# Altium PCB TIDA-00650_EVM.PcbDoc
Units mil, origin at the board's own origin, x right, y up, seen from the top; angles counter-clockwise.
Board outline 1549.21 x 1156.5 mil, 4 copper layers (Component Side, Ground Plane, Power Plane, Solder Side), stack 33.234 mil thick; 52 components, 27 nets, 148 pads, 47 vias.
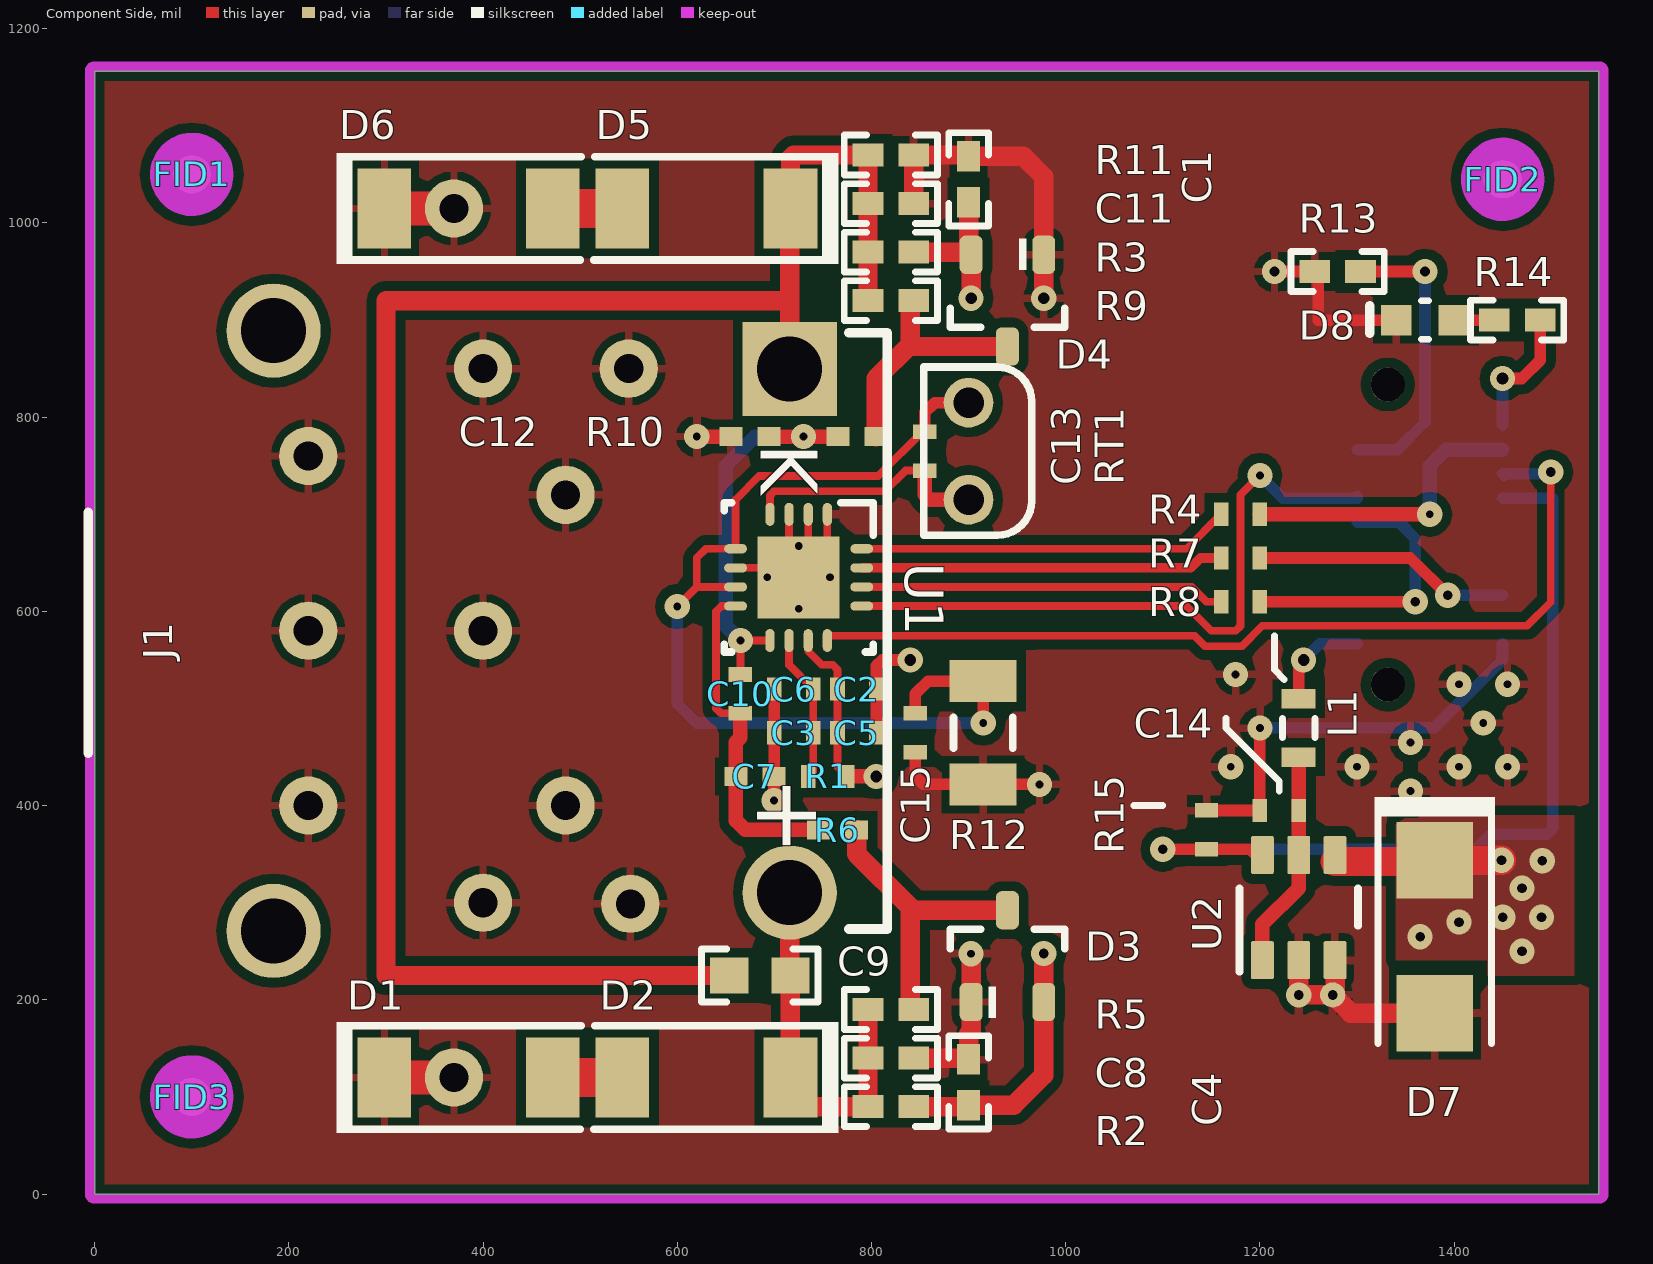
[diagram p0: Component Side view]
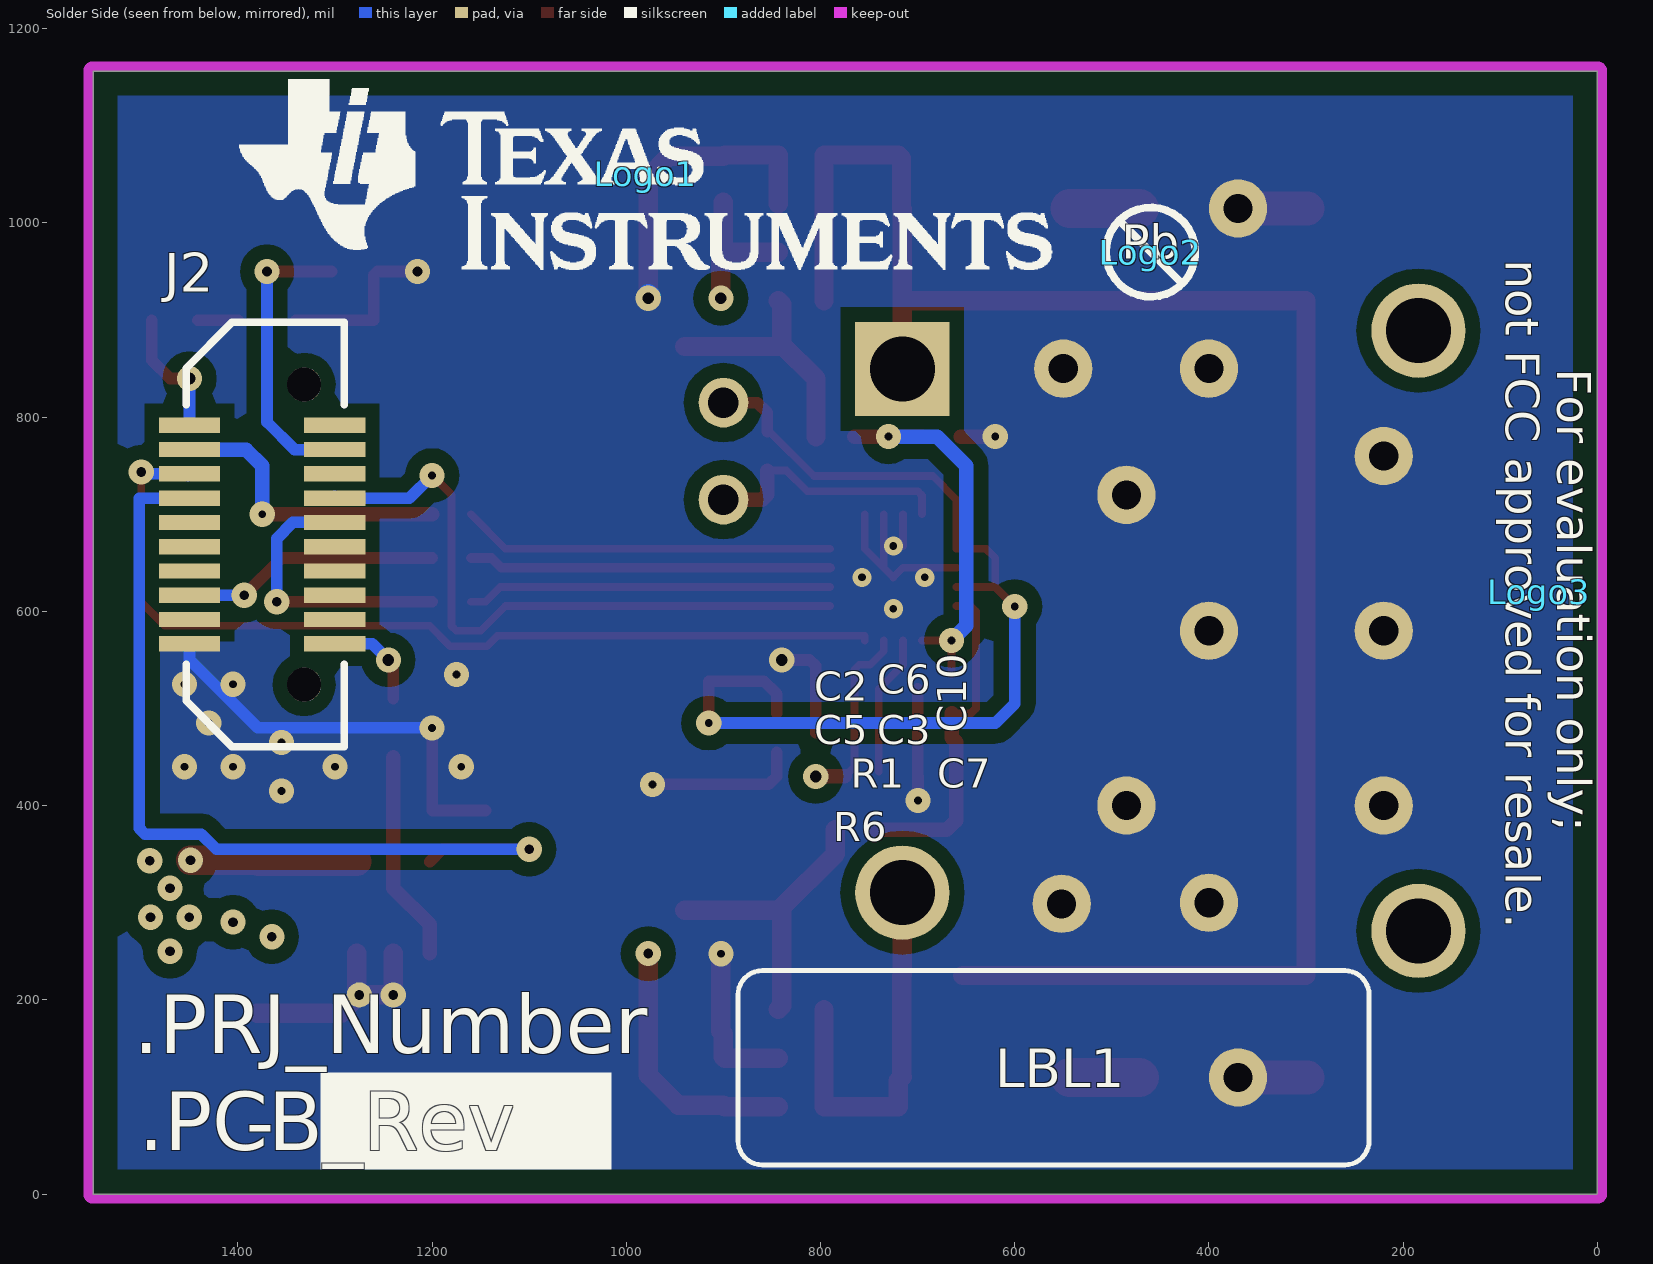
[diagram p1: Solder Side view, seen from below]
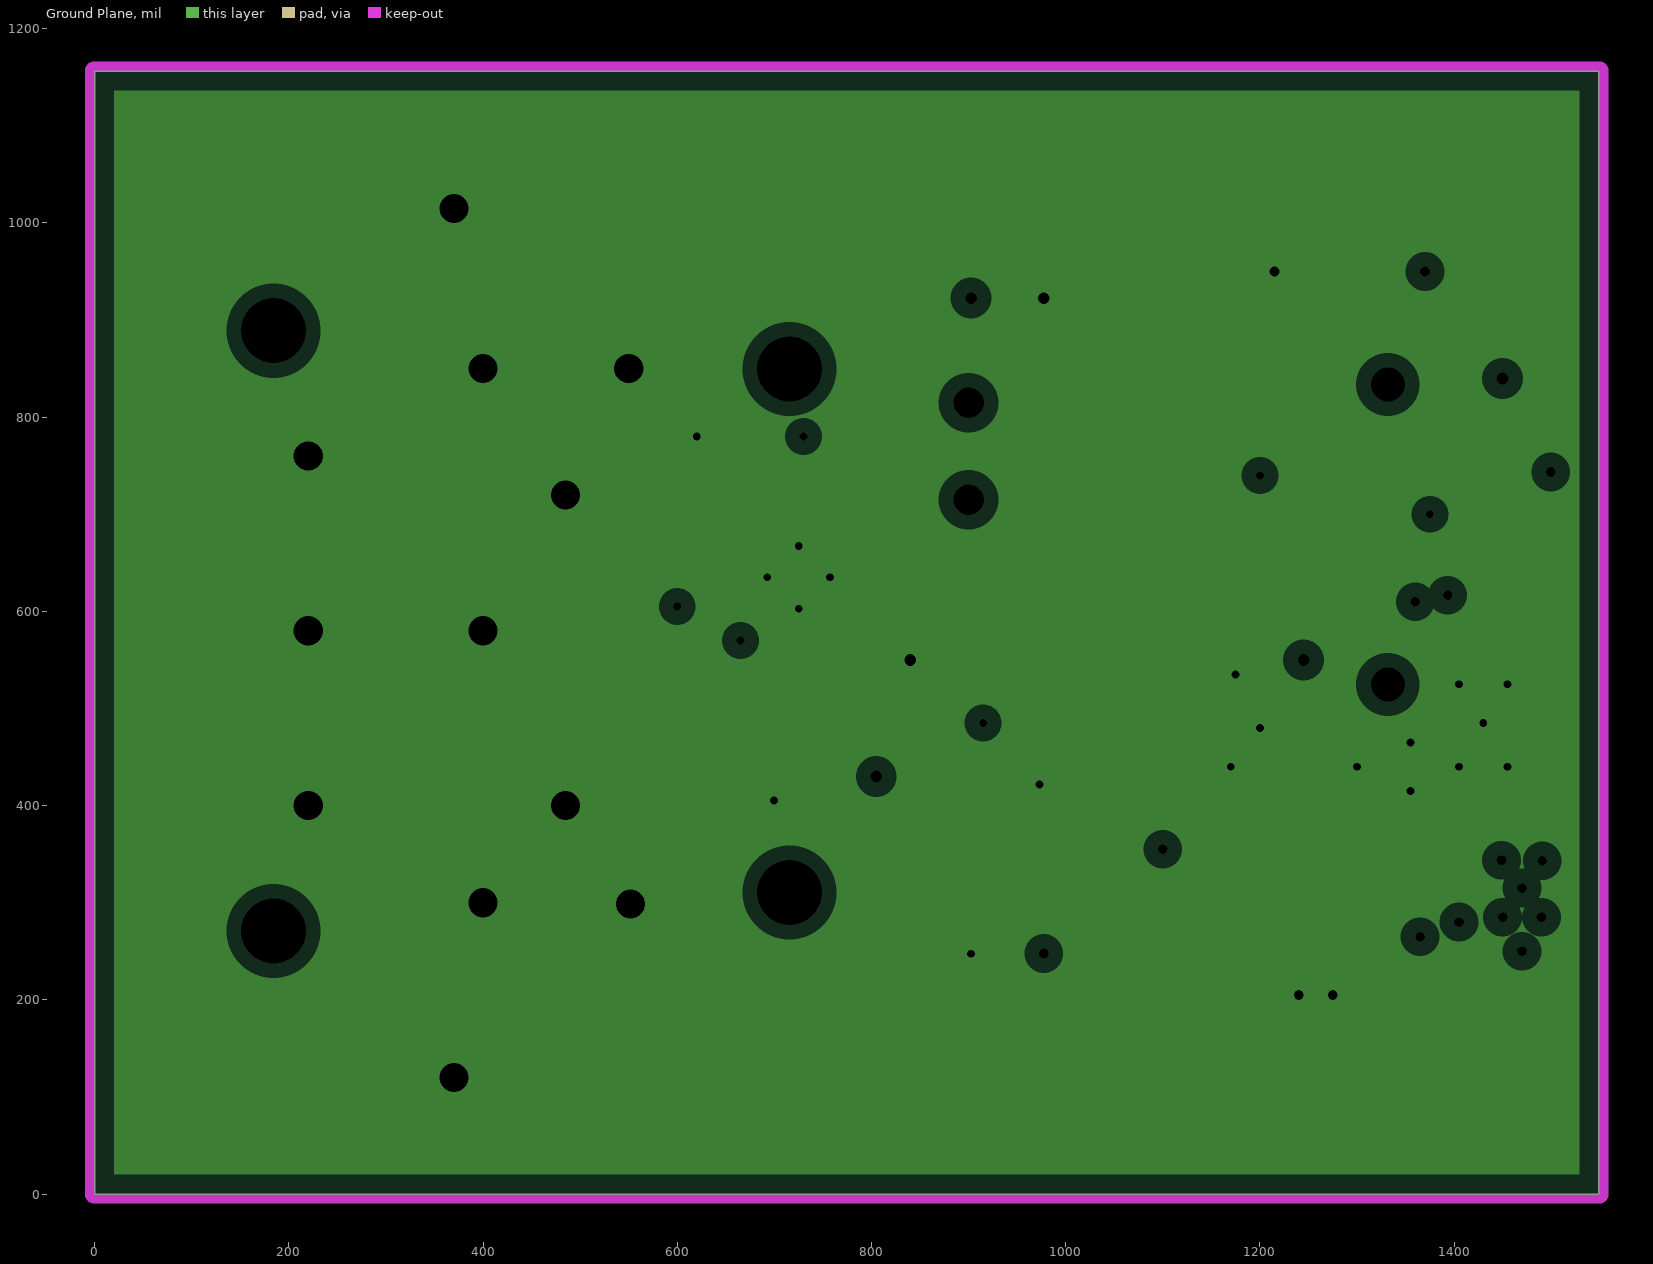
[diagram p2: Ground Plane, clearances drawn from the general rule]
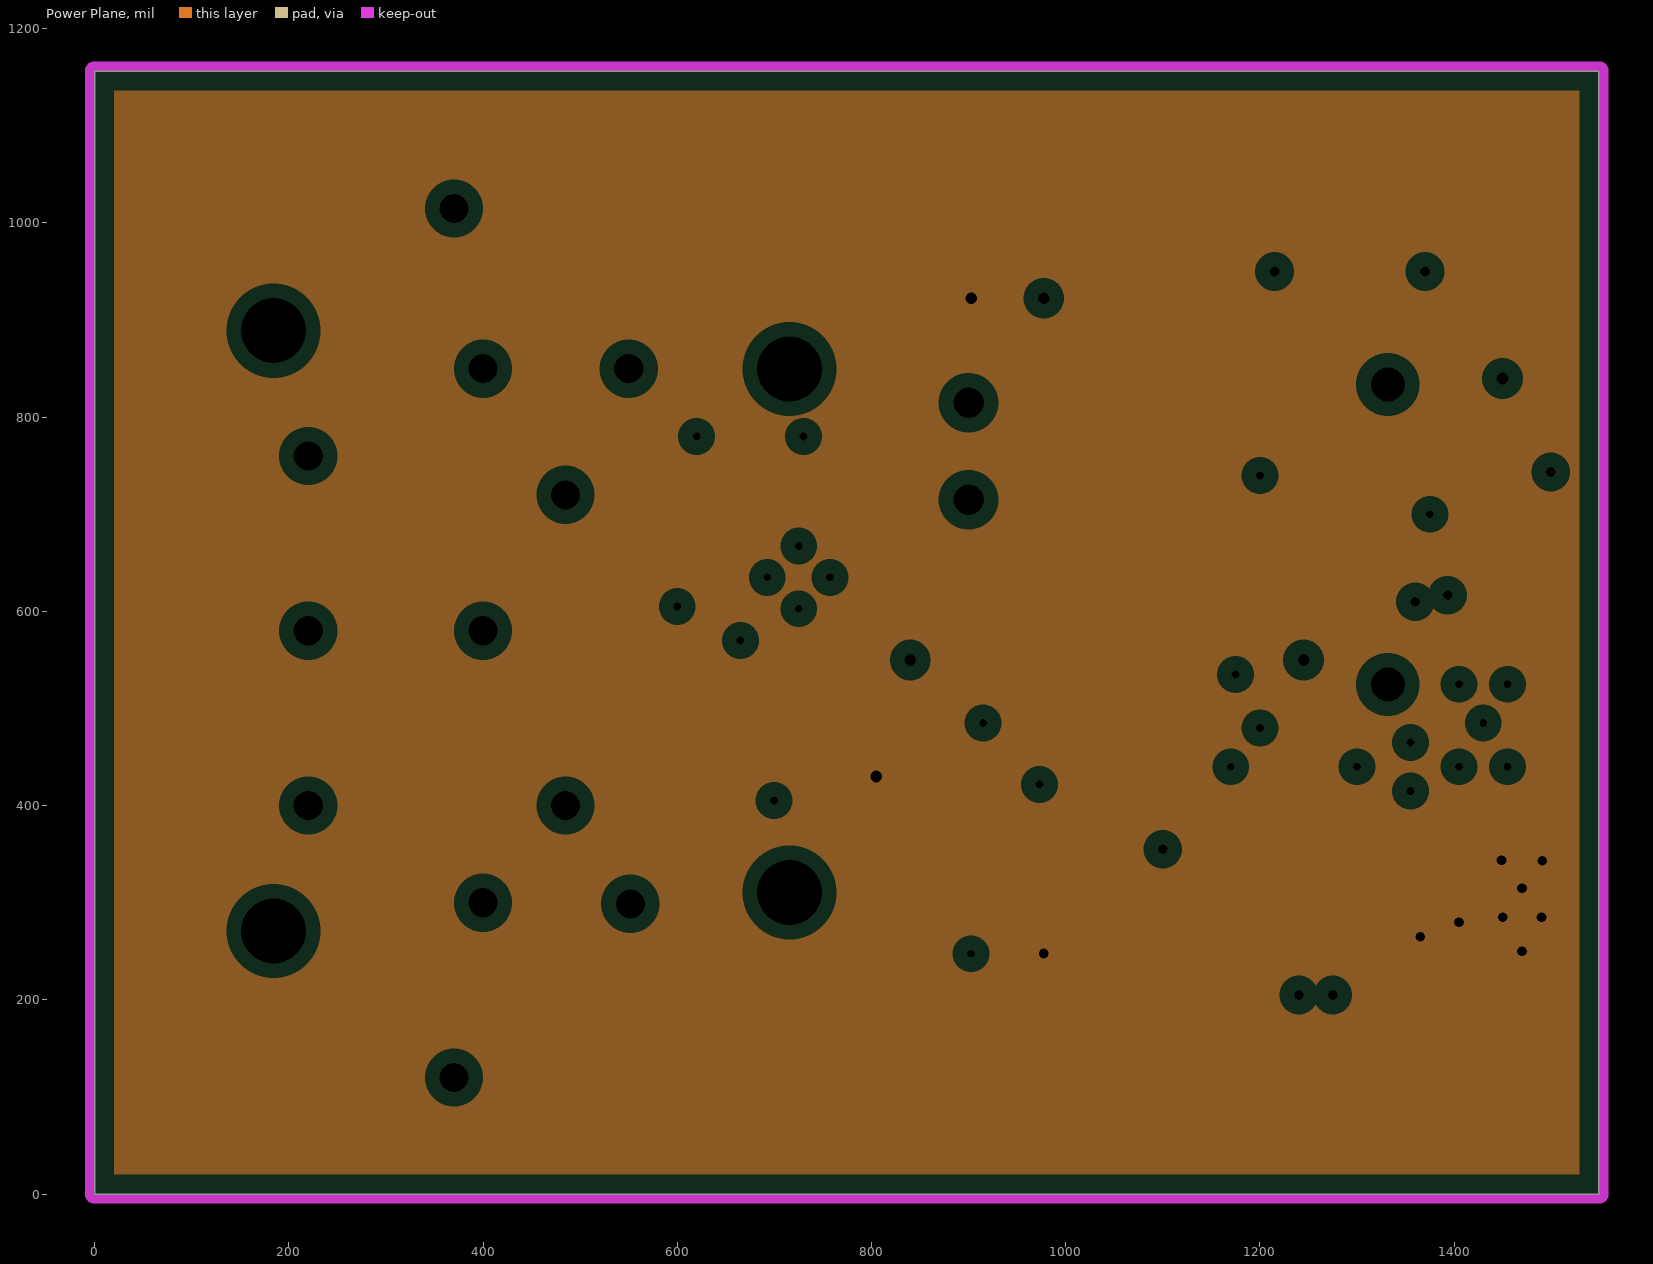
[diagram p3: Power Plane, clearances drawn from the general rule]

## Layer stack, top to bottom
Top Solder: solder mask 0.4, Solder Resist, Dk 3.5
Component Side: signal copper 1.4
Dielectric 1: core 12.6, FR-4, Dk 4.8
Ground Plane: plane copper 1.417, net GND
Dielectric 3: prepreg 5, Dk 4.2
Power Plane: plane copper 1.417, net VCC
Dielectric 4: core 10, Dk 4.2
Solder Side: signal copper 1.4
Bottom Solder: solder mask 0.4, Solder Resist, Dk 3.5

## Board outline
0,0 1549.21,0 1549.21,1156.5 0,1156.5

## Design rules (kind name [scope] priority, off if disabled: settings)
AcuteAngle [All] p1: minimum=4.50000000000000E+0001 checktracksonly=FALSE
AssemblyTestPointUsage [All] p1: valid=2
Clearance Clearance_1 [InNamedPolygon('Component Side-No Net')] p1: gap=10
Clearance Clearance_Keepouts [((IsTrack Or IsArc) And Not InPoly) And IsFree and IsKeepOut vs ((IsTrack Or IsArc) And Not InPoly) And IsFree and IsKeepOut] p2: gap=0
Clearance Clearance_BoardEdge_MountingHoles [OnCopper and InComponentClass('Mounting Holes') vs IsKeepOut] p3: gap=40
Clearance Clearance_BoardEdge_Poly [OnCopper and InPoly vs IsKeepOut] p4: gap=25
Clearance Clearance_BoardEdge [OnCopper and Not InComponentClass('Logo') and not InComponentClass('FiducialMark') and not InRegion(1000,500,4000,800) and Not IsKeepout vs IsKeepOut] p5: gap=35
Clearance Clearance_Poly [InPolygon] p6: gap=15
Clearance [All] p7: gap=7.87
ComponentClearance ComponentClearance_MountingHoles_FiducialMarks [InComponentClass('Mounting Holes') vs InComponentClass('FiducialMark')] p1: gap=50 collisioncheckmode=3 verticalgap=10 showdistances=FALSE
ComponentClearance ComponentClearance_Shunt [InComponentClass('Header') vs InComponentClass('Shunt')] p2: gap=0 collisioncheckmode=3 verticalgap=0 showdistances=FALSE
ComponentClearance ComponentClearance_Logo [InComponentClass('Logo')] p3: gap=50 collisioncheckmode=3 verticalgap=10 showdistances=FALSE
ComponentClearance ComponentClearance_ScrewToNut [(HasFootprint('NY PMS 440 0025 PH')) vs (HasFootprint('Keystone_1902C'))] p4: gap=5 collisioncheckmode=3 verticalgap=10 showdistances=FALSE
ComponentClearance ComponentClearance_MountingHoles [InComponentClass('Mounting Holes')] p5: gap=250 collisioncheckmode=3 verticalgap=100000 showdistances=FALSE
ComponentClearance ComponentClearance_SmallPassives [HasFootprint('0201*') or HasFootprint('0402*') or HasFootprint('0508') or HasFootprint('0603*') or HasFootprint('0612') or HasFootprint('0805*') or HasFootprint('0815*') or HasFootprint('0830*') or HasFootprint('1206*') or HasFootprint('1210*') or HasFootprint('1808*') or HasFootprint('1812*') or HasFootprint('1825*') or HasFootprint('2010*') or HasFootprint('2220*') or HasFootprint('2225*') or HasFootprint('2512*') or HasFootprint('2728*') or HasFootprint('3518*') vs HasFootprint('0201*') or HasFootprint('0402*') or HasFootprint('0508') or HasFootprint('0603*') or HasFootprint('0612') or HasFootprint('0805*') or HasFootprint('0815*') or HasFootprint('0830*') or HasFootprint('1206*') or HasFootprint('1210*') or HasFootprint('1808*') or HasFootprint('1812*') or HasFootprint('1825*') or HasFootprint('2010*') or HasFootprint('2220*') or HasFootprint('2225*') or HasFootprint('2512*') or HasFootprint('2728*') or HasFootprint('3518*')] p6: gap=20 collisioncheckmode=3 verticalgap=10 showdistances=FALSE
ComponentClearance ComponentClearance_THtoSMT [IsThruComponent vs IsSMTComponent] p7: gap=30 collisioncheckmode=3 verticalgap=30 showdistances=FALSE
ComponentClearance ComponentClearance_THtoTH [IsThruComponent vs IsThruComponent] p8: gap=40 collisioncheckmode=3 verticalgap=30 showdistances=FALSE
ComponentClearance [All] p9: gap=25 collisioncheckmode=3 verticalgap=10 showdistances=FALSE
DiffPairsRouting [All] p1: maxlimit=100 minlimit=10 mostfreqgap=10 toplayer_minwidth=15 toplayer_maxwidth=15 toplayer_prefwidth=15 bottomlayer_minwidth=15 bottomlayer_maxwidth=15 bottomlayer_prefwidth=15 maxuncoupledlength=1000
FabricationTestPointUsage TestPointUsage [All] p1: valid=2 allowmultiple=FALSE
FabricationTestpoint Testpoint [All] p1: side=3 testpointundercomponent=TRUE minsize=40 maxsize=100 preferedsize=60 minholesize=0 maxholesize=40 preferedholesize=32 testpointgrid=1 allowsidetop=TRUE allowsidebottom=TRUE usegrid=TRUE gridtolerance=0.01
FanoutControl Fanout_LCC [IsLCC] p1: bgadir=Out bgaviamode=Centered fanoutstyle=Auto fanoutdirection=Alternating viagrid=1 // Fanout_LCC (Default Rule)
FanoutControl Fanout_BGA [IsBGA] p2: bgadir=Out bgaviamode=Centered fanoutstyle=Auto fanoutdirection=Alternating viagrid=1 // Fanout_BGA (Default Rule)
FanoutControl Fanout_Default [All] p4: bgadir=Out bgaviamode=Centered fanoutstyle=Auto fanoutdirection=Alternating viagrid=1 // Fanout_Default (Default Rule)
FanoutControl Fanout_Small [(CompPinCount < 5)] p5: bgadir=Out bgaviamode=Centered fanoutstyle=Auto fanoutdirection=OutThenIn viagrid=1 // Fanout_Small (Default Rule)
HoleSize [All] p1: absolutevalues=TRUE maxlimit=251 minlimit=7.8 maxpercent=80.000 minpercent=20.000
MinimumAnnularRing MinimumAnnularRing_ThermalPadVias [IsVia and InAnyComponent] p1: minimumring=5.91
MinimumAnnularRing [All] p2: minimumring=6
MinimumSolderMaskSliver MinimumSolderMaskSliver_Logo [InComponentClass('Logo') vs InComponentClass('Logo')] p1: minsoldermaskwidth=0.7
MinimumSolderMaskSliver [All] p2 off: minsoldermaskwidth=3.94
PlaneClearance [All] p1: clearance=15
PlaneConnect [All] p1: planeconnectstyle=Relief reliefexpansion=10 reliefentries=4 reliefconductorwidth=10 reliefairgap=8
PolygonConnect PolygonConnect_9 [All vs IsNamedPolygon('Component Side-No Net 4')] p1: connectstyle=Direct reliefconductorwidth=10 reliefentries=4 polygonreliefangle="90 Angle" airgapwidth=10
PolygonConnect PolygonConnect_8 [All vs IsNamedPolygon('Component Side-No Net 4')] p2: connectstyle=Relief reliefconductorwidth=8 reliefentries=4 polygonreliefangle="90 Angle" airgapwidth=7
PolygonConnect PolygonConnect_7 [All vs IsNamedPolygon('Component Side-No Net 3')] p3: connectstyle=Relief reliefconductorwidth=8 reliefentries=4 polygonreliefangle="90 Angle" airgapwidth=7
PolygonConnect PolygonConnect_6 [All vs IsNamedPolygon('Component Side-No Net 3')] p4: connectstyle=Relief reliefconductorwidth=8 reliefentries=4 polygonreliefangle="90 Angle" airgapwidth=8
PolygonConnect PolygonConnect_5 [All vs IsNamedPolygon('Solder Side-No Net 1')] p5: connectstyle=Direct reliefconductorwidth=10 reliefentries=4 polygonreliefangle="90 Angle" airgapwidth=10
PolygonConnect PolygonConnect_4 [All vs IsNamedPolygon('Solder Side-No Net')] p6: connectstyle=Direct reliefconductorwidth=10 reliefentries=4 polygonreliefangle="90 Angle" airgapwidth=10
PolygonConnect PolygonConnect_3 [All vs IsNamedPolygon('Component Side-No Net')] p7: connectstyle=Relief reliefconductorwidth=8 reliefentries=4 polygonreliefangle="90 Angle" airgapwidth=8
PolygonConnect PolygonConnect_2 [All vs IsNamedPolygon('Component Side-No Net 1')] p8: connectstyle=Relief reliefconductorwidth=8 reliefentries=4 polygonreliefangle="90 Angle" airgapwidth=8
PolygonConnect PolygonConnect_1 [All vs IsNamedPolygon('Component Side-No Net 1')] p9: connectstyle=Relief reliefconductorwidth=10 reliefentries=4 polygonreliefangle="90 Angle" airgapwidth=8
PolygonConnect [All] p10: connectstyle=Relief reliefconductorwidth=10 reliefentries=4 polygonreliefangle="90 Angle" airgapwidth=10
RoutingVias ThermalPadVias [IsVia and InAnyComponent] p1: holewidth=7.87 width=19.68 viastyle="Through Hole" minholewidth=7.87 minwidth=19.68 maxholewidth=12.99 maxwidth=23.62
RoutingVias [All] p2: holewidth=16 width=34 viastyle="Through Hole" minholewidth=7.87 minwidth=26 maxholewidth=40 maxwidth=65
SilkToBoardRegionClearance [Not ((IsComment or IsDesignator) And (Hide <> 'False')) and not InRegion(1000,500,4000,800)] p1 off:
SilkToSilkClearance SilkToSilkClearance_Pb-FreeLogo [(HasFootprint('Pb-Free_Overlay_Medium') OR HasFootprint('Pb-Free_Overlay_Small')) vs (HasFootprint('Pb-Free_Overlay_Medium') OR HasFootprint('Pb-Free_Overlay_Small'))] p1: silktosilkclearance=0
SilkToSilkClearance [All] p2: silktosilkclearance=5
SilkToSolderMaskClearance "Silk to Solder Mask Opening" [All] p1 off: minsilkscreentomaskgap=1 clearancetoexposedcopper=FALSE
SolderMaskExpansion [All] p1: expansion=1.97
UnpouredPolygon [All] p1: allowunpoured=FALSE
Width [All] p1: maxlimit=100 minlimit=6 preferedwidth=10 checkconnectedcopper=TRUE
13 further rules are at their usual default settings.

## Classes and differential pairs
component class Label: LBL1
component class AssemblyNote: ZZ1
component class FiducialMark: FID1 FID2 FID3
component class TIDA-00650_EVM_Hardware: FID1 FID2 FID3 LBL1 Logo1 Logo2 Logo3 ZZ1
component class Logo: Logo1
component class TIDA-00650_ADC: C1 C2 C3 C4 C5 C6 C7 C8 C9 C10 C11 C12 C13 C14 C15 D1 D2 D3 D4 D5 D6 D7 D8 J1 J2 L1 R1 R2 R3 R4 R5 R6 R7 R8 R9 R10 R11 R12 R13 R14 R15 RT1 U1 U2

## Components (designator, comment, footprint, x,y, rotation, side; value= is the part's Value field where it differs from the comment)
C1 "C1005X7R1H104K050BB" 0402 900,1045 r270 top
C2 "GRM155R61A105KE15D" 0402S 785,520 r180 top
C3 "GRM155R61A105KE15D" 0402S 720,475 r180 top
C4 "C1005X7R1H104K050BB" 0402 900,115 r270 top
C5 "GRM155R60J224KE01D" 0402S 785,475 r180 top
C6 "GRM155R60J224KE01D" 0402S 720,520 r180 top
C7 "GRM155R60J274KE01D" 0402L 680,430 r180 top
C8 "C1005X7R1H104K050BB" 0402 820,140 r180 top
C9 "UMK107AB7105KA-T" 0603 685,225 r180 top
C10 "C1005X5R1A475K050BC" 0402S 665,515 r90 top
C11 "C1005X7R1H104K050BB" 0402 820,1020 r0 top
C12 "GRM155R60J274KE01D" 0402L 675,780 r180 top
C13 "GRM155R61A105KE15D" 0402S 855,765 r90 top
C14 "GRM155R61A106ME11" 0402S 1220,395 r180 top
C15 "GRM155R61A105KE15D" 0402S 845,475 r270 top
D1 "PTVS13VP1UP_115" SOD-128 385,120 r0 top
D2 "PTVS13VP1UP_115" SOD-128 630,120 r180 top
D3 "BAV199-TP" SOT-23 940,245 r90 top
D4 "BAV199-TP" SOT-23 940,920 r270 top
D5 "PTVS13VP1UP_115" SOD-128 630,1015 r180 top
D6 "PTVS13VP1UP_115" SOD-128 385,1015 r0 top
D7 "PTZTE253.6B" SMA 1380,265 r270 top
D8 "LG L29K-G2J1-24-Z" "LG L29K_GREEN" 1370,900 r180 top
FID1 "Fiducial" Fiducial10-20 100,1050 r0 top
FID2 "Fiducial" Fiducial10-20 1450,1045 r0 top
FID3 "Fiducial" Fiducial10-20 100,100 r0 top
J1 "PCC-SMP-K-5-R" Omega_PCC-SMP-K 450,580 r270 top
J2 "LSS-110-01-F-DV-A" Samtec_LSS-110-01-F-DV-A 1375,679.13 r90 bottom
L1 "BLM18BB050SN1D" 0603S 1240,480 r270 top
LBL1 "Size: 0.65\" x 0.20 \"" Label_650x200 560,130 r180 bottom
Logo1 "Texas Instruments" TI_Stacked_Overlay_Small 980,1050 r180 bottom
Logo2 "Pb-Free Symbol" Pb-Free_Overlay_Small 460,970 r180 bottom
Logo3 "FCC disclaimer" FCC_disclaimer_stacked 60,620 r270 bottom
R1 "CRCW040210R0FKED" 0402S 755,430 r0 top
R2 "CRCW04022M00FKED" 0402 820,90 r0 top
R3 "CRCW04022M00FKED" 0402 820,970 r0 top
R4 "CRCW040247R0JNED" 0402S 1180,700 r0 top
R5 "CRCW0402499RFKED" 0402 820,190 r0 top
R6 "CRCW0402499RFKED" 0402L 765,375 r180 top
R7 "CRCW040247R0JNED" 0402S 1180,655 r0 top
R8 "CRCW040247R0JNED" 0402S 1180,610 r0 top
R9 "CRCW0402499RFKED" 0402 820,920 r0 top
R10 "CRCW0402499RFKED" 0402L 785,780 r180 top
R11 "CRCW04022M00FKED" 0402 820,1070 r180 top
R12 "PFC-W1206R-12-3241-B" 1206L 915,475 r90 top
R13 "CRCW0402240KFKED" 0402 1280,950 r0 top
R14 "ERJ-2RKF4700X" 0402 1465,900 r0 top
R15 "CRCW04022M20JNED" 0402S 1145,375 r270 top
RT1 "32209210" TO-92_Heraeus 900,765 r270 top
U1 "ADS1220IRVAR" RVA0016A 725,635 r270 top
U2 "TS5A3159DBVR" DBV0006A_N 1240,295 r90 top
ZZ1 "This Assembly Note is for PCB labels only" AssemblyNoteLabel 185,1620 r0 top

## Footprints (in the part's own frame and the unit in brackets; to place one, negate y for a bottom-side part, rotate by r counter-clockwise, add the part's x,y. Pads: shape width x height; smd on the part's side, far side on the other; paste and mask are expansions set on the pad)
0402 [mm] "0402 from SM-752 data"
  rect 0.8x0.6 smd: 1(-0.6,0) 2(0.6,0)
  silkscreen extent -1.22,-0.52 1.22,0.52, body extent -0.55,-0.3 0.55,0.3, height 0.6
0402L [mm] "0402 from SM-752 data"
  rect 0.6x0.5 smd: 1(-0.5,0) 2(0.5,0)
  body extent -0.55,-0.3 0.55,0.3, height 0.6
0402S [mil] "Based on C0402S footprint from PADS legacy"
  rect 15x24 smd: 1(-20,0) 2(20,0)
  body extent -22,-12 22,12, height 24
0603 [mm] "0603 from SM-752 data"
  rect 1x0.95 smd: 1(-0.8,0) 2(0.8,0)
  silkscreen extent -1.52,-0.69 1.52,0.69, body extent -0.87,-0.47 0.87,0.47, height 1
0603S [mil]
  rect 20x35 smd: 1(-30,0) 2(30,0)
  silkscreen extent -10,-17 10,17, body extent -34,-19 34,19, height 39
1206L [mm] "1206 from SM-752 data"
  rect 1.1x1.75 smd: 1(-1.35,0) 2(1.35,0)
  silkscreen extent -0.4,-0.77 0.4,0.77, body extent -1.7,-0.9 1.7,0.9, height 1.35
AssemblyNoteLabel [mil] "Assembly Note for PCB Labels"
DBV0006A_N [mm] "SOT23, 6-Leads, Body 2.9x1.6mm, Pitch 0.95mm, Lead Span 2.8mm, IPC Medium Density"
  rrect17% 1x0.6 smd: 1(-1.375,0.95) 2(-1.375,0) 3(-1.375,-0.95) 4(1.375,-0.95) 5(1.375,0) 6(1.375,0.95)
  silkscreen extent -1.68,-1.55 0.5,1.55, body extent -1.42,-1.46 1.42,1.46, height 1.12
FCC_disclaimer_stacked [mil]
Fiducial10-20 [mm]
  round 1 smd mask+0.5: 1(0,0)
  Component Side keep-out circle w1.178: c0,0 r0.5
Label_650x200 [mil] "Thermal Transfer Label"
  round 1 on Mech14: 0(0,0)
  silkscreen extent -325,-100 325,100, body extent -326,-101 326,101, height 1
"LG L29K_GREEN" [mm] "OSRAM"
  rect 0.8x0.8 smd paste-0.4: 1(-0.75,0) 2(0.75,0)
  silkscreen extent -0.1,-0.5 1.45,0.5, body extent -0.9,-0.45 0.9,0.45, height 0.67
Omega_PCC-SMP-K [mm] "Omega"
  rect 2.464x2.464 hole 1.7: 1(-6.85,6.75)
  round 2.464 hole 1.7: 2(6.85,6.75) 3(-7.85,-6.75) 4(7.85,-6.75)
  silkscreen extent -7.8,-11.6 7.8,9.3, body extent -7.8,-11.57 7.75,9.23, height 6.35
Pb-Free_Overlay_Small [mil]
  silkscreen extent -46,-46 46,46
RVA0016A [mm] "QFN, 16-Leads, Body 3.5x3.5mm, Pitch 0.5mm, Thermal Pad 2.14x2.14mm, TI Recommended"
  oval 0.6x0.24 smd: 1(-1.65,0.75) 2(-1.65,0.25) 3(-1.65,-0.25) 4(-1.65,-0.75) 9(1.65,-0.75) 10(1.65,-0.25) 11(1.65,0.25) 12(1.65,0.75)
  oval 0.24x0.6 smd: 5(-0.75,-1.65) 6(-0.25,-1.65) 7(0.25,-1.65) 8(0.75,-1.65) 13(0.75,1.65) 14(0.25,1.65) 15(-0.25,1.65) 16(-0.75,1.65)
  rect 2.14x2.14 smd paste-1.07: 17(0,0)
  silkscreen extent -1.95,-1.95 1.95,1.95, body extent -1.8,-1.8 1.8,1.8, height 1.01
Samtec_LSS-110-01-F-DV-A [mm] "Samtec"
  rect 0.4x1.6 smd: 1(-2.857,1.9) 2(-2.857,-1.9) 3(-2.222,1.9) 4(-2.222,-1.9) 5(-1.587,1.9) 6(-1.588,-1.9) 7(-0.952,1.9) 8(-0.953,-1.9) 9(-0.317,1.9) 10(-0.318,-1.9) 11(0.318,1.9) 12(0.317,-1.9) 13(0.953,1.9) 14(0.952,-1.9) 15(1.588,1.9) 16(1.587,-1.9) 17(2.222,1.9) 18(2.222,-1.9) 19(2.857,1.9) 20(2.857,-1.9)
  round 0.89 hole 0.89 unplated: MH-1(3.925,-1.1) MH-2(-3.925,-1.1)
  silkscreen extent -5.55,-2.15 5.55,1.99, body extent -5.55,-2.3 5.55,2.3, height 4.46
SMA [mm] "Molded Diode, 2-Leads, Body 4.3x2.6mm, IPC Medium Density, based on OnSemi component dimensions and land pattern"
  rect 2x2 smd: 1(-2,0) 2(2,0)
  silkscreen extent -3.66,-1.57 2.79,1.57, body extent -2.6,-1.3 2.6,1.3, height 2.42
SOD-128 [mm] "SMD, 2-Leads, Body 4x2.7mm, Height 1.1mm"
  rect 1.4x2.1 smd paste-0.1: 1(-2.2,0) 2(2.2,0)
  silkscreen extent -3.45,-1.45 2.95,1.45, body extent -2.5,-1.35 2.5,1.35, height 1.1
SOT-23 [mm] "SOT23, 3-Leads, Body 2.9x1.3mm, Pitch 0.95mm, Lead Span 2.5mm, IPC Medium Density"
  rrect50% 1x0.6 smd: 1(-1.2,0.95) 2(-1.2,-0.95) 3(1.2,0)
  silkscreen extent -1.62,-1.5 0.7,1.5, body extent -1.16,-1.45 1.21,1.45, height 1
TI_Stacked_Overlay_Small [mil]
  silkscreen extent -418,-98 418,98
TO-92_Heraeus [mm] "Heraeus"
  round 1.3 hole 0.8: 1(-1.27,0) 2(1.27,0)
  silkscreen extent -2.2,-1.17 2.2,1.65, body extent -2.2,-1.17 2.2,1.63, height 5.9

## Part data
C1 C4 C8 C11: "CAP, CERM, 0.1 µF, 50 V, +/- 10%, X7R, 0402"
C2 C3 C13 C15: "CAP, CERM, 1 µF, 10 V, +/- 10%, X5R, 0402"
C5 C6: "CAP, CERM, 0.22 µF, 6.3 V, +/- 10%, X5R, 0402"
C7 C12: "CAP, CERM, 0.27 µF, 6.3 V, +/- 10%, X5R, 0402"
C9: "CAP, CERM, 1 µF, 50 V, +/- 10%, X7R, 0603"
C10: "CAP, CERM, 4.7 µF, 10 V, +/- 10%, X5R, 0402"
C14: "CAP, CERM, 10 µF, 10 V, +/- 20%, X5R, 0402"
D1 D2 D5 D6: "Diode, TVS, Uni, 13 V, 600 W, SOD-128"
D3 D4: "Diode, Switching, 70 V, 0.215 A, SOT-23"
D7: "Diode, Zener, 3.813 V, 1 W, SMA"
D8: "LED, Green, SMD"
FID1 FID2 FID3: "Fiducial mark.  There is nothing to buy or mount."
J1: "Circuit Board Thermocouple Connector, Miniature Size, Type K, Horizontal installation, TH"
J2: "Terminal/Socket Combo, 25mil, 10x2, Gold, SMT"
L1: "Ferrite Bead, 5 ohm @ 100 MHz, 0.7 A, 0603"
LBL1: library part THT-14-423-10, "Thermal Transfer Printable Labels, 0.650\" W x 0.200\" H - 10,000 per roll"
Logo1: library part TI_Logo, "Texas Instrument Corporate Signature"
Logo2: library part Pb-Free
Logo3: library part FCC_disclaimer, "FCC_disclaimer"
R1: "RES, 10.0, 1%, 0.063 W, 0402"
R2 R3 R11: "RES, 2.00 M, 1%, 0.063 W, 0402"
R4 R7 R8: "RES, 47, 5%, 0.063 W, 0402"
R5 R6 R9 R10: "RES, 499, 1%, 0.063 W, 0402"
R12: "RES, 3.24 k, 0.1%, 0.333 W, 1206"
R13: "RES, 240 k, 1%, 0.063 W, 0402"
R14: "RES, 470, 1%, 0.1 W, 0402"
R15: "RES, 2.2 M, 5%, 0.063 W, 0402"
RT1: "Temperature Sensor, 100ohm, TC=+3850ppm, TO-92, TH"
U1: "Low-Power, Low-Noise, 24-Bit Analog-to-Digital Converter for Small Signal Sensors, RVA0016A"
U2: "1-? SPDT Analog Switch, DBV0006A"
ZZ1: library part AssemblyNoteLabel

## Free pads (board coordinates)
  round 60 hole 30: 0(220,400) 0(550,850) 1(220,760) 1(551.67,298.85) 2(220,580) 3(485,400) 5(370,120) 5(370,1015) 5(400,300) 6(400,580) 7(400,850) 8(485,720)
  round 26 hole 10: 0(1275,205)

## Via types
v1: diameter 26, hole 8, Component Side to Solder Side, 21 vias
v2: diameter 26, hole 10, Component Side to Solder Side, 16 vias
v3: diameter 26, hole 12, Component Side to Solder Side, 6 vias
v4: diameter 19.68, hole 7.87, Component Side to Solder Side, 4 vias

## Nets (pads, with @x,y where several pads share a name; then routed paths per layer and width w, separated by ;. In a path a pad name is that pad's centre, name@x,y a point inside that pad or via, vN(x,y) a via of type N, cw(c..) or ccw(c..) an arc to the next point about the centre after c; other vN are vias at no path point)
+: C8.2 C9.1 D2.1 J1.2 R2.1 R5.1 | length 398
  Component Side w20: C9.1@715.75,225.75 J1.2 ; C9.1 716.5,121.61 715.75,120.87 D2.1 720,116.61 720,90 R2.1 R5.1
AIN0: C10.2 C12.1 R10.2 U1.9 | length 414.7
  Component Side w8: C10.2 C10.2 v1(665.04,570.04) U1.9
  Component Side w15: C12.1 v1(730,780) R10.2
  Solder Side w15: v1(665.04,570.04) 650,585.08 650,750 680,780 v1(730,780)
AIN1: C7.2 C10.1 R6.2 U1.8 | length 350.6
  Component Side w8: U1.8 645.47,605.47 640,600 640,500 645,495 C10.1
  Component Side w15: C10.1 665,470 660.31,465.31 C7.2 660.31,384.69 670,375 R6.2
AIN2: C13.2 C15.1 R12.2 RT1.1 U1.5 U1.7 | length 1047.6
  Component Side w8: v1(600,605) 620.16,625.16 ; U1.7 620.16,625.16 ; C13.2 852.55,785 807.07,739.52 684.52,739.52 660.04,715.04 U1.5 629.53,664.53 620.16,655.16 620.16,625.16
  Component Side w12: C15.1 845,515 858.15,528.15 R12.2 v1(915,485) ; C13.2 855,805 865,815 RT1.1
  Solder Side w12: v1(600,605) 600,505 620,485 v1(915,485)
AIN3: C13.1 RT1.2 U1.4 | length 261.6
  Component Side w8: U1.4 695.47,719.39 699.73,723.65 813.65,723.65 835,745 C13.1
  Component Side w15: C13.1 855,720 860,715 RT1.2
DIN_ADC: J2.12 R8.2 | length 291.7
  Component Side w12: R8.2 v2(1360,610)
  Solder Side w12: J2.12 1343.37,691.63 1360,675 v2(1360,610)
DOUT_ADC: J2.14 U1.13 | length 677.7
  Component Side w8: U1.13 1124.53,605.47 1150,580 1175,580 1180,585 1180,720 v1(1200,740)
  Solder Side w12: v1(1200,740) 1223.37,716.63 J2.14 J2.14@1300.2,718.51
GND: C1.1 C2.1 C3.2 C4.1 C5.1 C6.2 C7.1 C8.1 C11.2 C12.2 C14.2 C15.2 D1.1 D3.1 D4.1 D6.1 D7.2 D8.2 J2.1 pad.0 pad.1 pad.2 pad.3 pad.5 pad.6 pad.7 pad.8 R11.1 R12.1 R13.1 R15.1 U1.1 U1.2 U1.3 U1.6 U1.17 U2.2 U2.3 | length 2118.2
  Component Side w8: U1.6 715.16,644.84 U1.17 U1.17@734.84,644.84 ; U1.17@715.16,667.28 U1.3 ; U1.2 U1.17@734.84,644.84 ; U1.1 754.53,664.53 U1.17@734.84,644.84
  Component Side w12: v1(699.68,405.32) C7.1 ; C7.1@700,430.32 C6.2 ; C5.1 C2.1 805,543.86 811.14,550 v3(840,550) ; C15.2 845,430 853.15,421.85 v1(973.15,421.85) ; R15.1 C14.2 v1(1200,480) ; v2(1215,950) R13.1 1260,946.38 1260,900 D8.2
  Component Side w15: v1(620,780) C12.2
  Component Side w20: C8.1 898.62,140 900,141.38 900,165 902.6,167.6 D3.1 v1(902.6,247.4) ; C11.2 R11.1 898.62,1070 C1.1 956.38,1068.62 977.4,1047.6 D4.1 v3(977.4,922.4) ; U2.2@1240,247.76 v2(1240,205) 1275,205 1293.74,186.26 D7.2 ; pad.0@1277.4,207.4 U2.3@1277.4,247.76
  Component Side w35: D1.1 pad.5@370,120 ; D6.1 pad.5@370,1015
  Solder Side w12: v1(699.68,405.32) v1@700,405 ; v1@968.15,421.85 v1@970,420 ; v1(1200,480) 1379.61,480 1449.8,550.2 J2.1
  Solder Side w20: v3@975,925 v3@977.4,927.4
  other v1: 1355,415 1170,440 1300,440 1405,440 1455,440 1355,465 1430,485 1405,525 1455,525 1175,535
  other v4: 725,602.72 692.72,635 757.28,635 725,667.28
K: C9.2 C11.1 D5.1 J1.1 R3.1 R9.1 R11.2 | length 1912.7
  Component Side w20: C9.2 300,225 300,920 715.75,920 ; J1.1 715.75,920 ; R9.1 R3.1 C11.1 R11.2 720,1070 716.61,1066.61 D5.1 715.75,1014.13 715.75,920
LED: J2.19 R14.2 | length 136.2
  Component Side w12: v3(1449.8,839.8) 1469.8,839.8 1488.62,858.62 R14.2
  Solder Side w12: J2.19 v3(1449.8,839.8)
NCS_ADC: J2.17 R4.2 | length 306.7
  Component Side w15: R4.2 v1(1375,700)
  Solder Side w15: v1(1375,700) 1375,750 1391.63,766.63 J2.17
NDRDY_ADC: J2.15 U1.12 | length 959.9
  Component Side w8: U1.12 754.53,574.87 1132.68,574.87 1143.42,564.13 1181.58,564.13 1202.58,585.13 1475.13,585.13 1499.57,609.57 v2(1499.57,743.51)
  Solder Side w12: J2.15@1451.44,740 J2.15 1497.69,741.63 v2(1499.57,743.51)
NetC3_1: C3.1 C6.1 R1.1 U1.10 | length 145.3
  Component Side w8: U1.10 715.16,544.84 C6.1 C3.1 R1.1@740,435
NetD1_2: D1.2 D2.2 | length 71.8
  Component Side w40: D1.2 D2.2
NetD3_3: D3.3 R5.2 R6.1 | length 310.6
  Component Side w20: R6.1 784.68,350.32 840,295 ; R5.2 840,193.62 840,295 ; D3.3 842.76,292.24 840,295
NetD4_3: D4.3 R9.2 R10.1 | length 257.1
  Component Side w20: R10.1 804.68,839.68 840,875 ; R9.2 840,916.38 840,875 ; D4.3 842.24,872.76 840,875
NetD5_2: D5.2 D6.2 | length 71.8
  Component Side w40: D6.2 D5.2
NetD8_1: D8.1 R14.1 | length 41.9
  Component Side w12: D8.1 R14.1
NetJ2_2: J2.2 L1.1 | length 104.2
  Component Side w12: L1.1 1240,545 v3(1245,550)
  Solder Side w12: v3(1245,550) 1261.63,566.63 J2.2
NetJ2_18: J2.18 R13.2 | length 302.9
  Component Side w12: R13.2 v2(1370,950)
  Solder Side w12: J2.18 1341.63,766.63 1370,795 v2(1370,950)
NetR4_1: R4.1 U1.16 | length 384.7
  Component Side w8: U1.16 1124.53,664.53 R4.1
NetR7_1: R7.1 U1.15 | length 374.2
  Component Side w10: U1.15 1128.71,644.84 1138.86,655 R7.1
NetR8_1: R8.1 U1.14 | length 376.3
  Component Side w8: U1.14 1129.84,625.16 1145,610 R8.1
PWR_UP_CHIP: J2.13 R15.2 U2.6 | length 910.2
  Component Side w12: v2(1100,355) R15.2 1189.84,355 U2.6@1202.6,342.24
  Solder Side w12: v2(1100,355) 1421.99,355 1437.61,370.61 1495.61,370.61 1501.58,376.58 1501.58,716.63 J2.13
SCLK_ADC: J2.5 R7.2 | length 265.7
  Component Side w12: R7.2 1355,655 v2(1393.37,616.63)
  Solder Side w12: v2(1393.37,616.63) J2.5
VCC: C1.2 C2.2 C4.2 C5.2 D3.2 D4.2 D7.1 R1.2 R2.2 R3.2 U1.11 U2.4 | length 789.9
  Component Side w8: U1.11 734.84,559.03 748.87,545 760,545 765,540 C2.2 C5.2 765,440 R1.2
  Component Side w15: R1.2 v3(805,430)
  Component Side w20: R2.2 898.62,90 C4.2 946.38,91.38 977.4,122.4 D3.2 v2(977.4,247.6) ; R3.2 899.84,970 900,970.16 C1.2 ; v3(902.6,922.6) D4.2
  Component Side w30: U2.4@1277.4,342.24 1378.5,342.24 D7.1 v2(1448.74,343.74)
  other v2: 1470,250 1365,265 1405,280 1450,285 1490,285 1470,315 1490.75,343.13
VDD_SENSORTAG: C14.1 L1.2 U2.1 U2.5 | length 217.7
  Component Side w15: U2.1@1202.6,247.76 1202.6,277.6 1240,315 1240,342.24 L1.2
pads on no net: FID1.1 FID2.1 FID3.1 J1.3 J1.4 J2.3 J2.4 J2.6 J2.7 J2.8 J2.9 J2.10 J2.11 J2.16 J2.20 J2.MH-1 J2.MH-2 LBL1.0

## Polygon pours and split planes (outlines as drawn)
VCC on Component Side "Component Side-No Net 4" (solid, remove dead copper, pour order 4): 1340,390 1550,390 1550,225 1340,225
GND on Component Side "Component Side-No Net" (solid, remove dead copper, pour order 13): 0,1156.5 1549.21,1156.5 1549.21,0 0,0
GND on Solder Side "Solder Side-No Net" (solid, remove dead copper, pour order 8): 1490,560 1490,385 1150,385 1150,560
GND on Solder Side "Solder Side-No Net 1" (solid, remove dead copper, pour order 10): 0,1156.5 1549.21,1156.5 1549.21,0 0,0
GND on Ground Plane (split plane): 1529.11,20.1 20.1,20.1 20.1,1136.4 1529.11,1136.4
VCC on Power Plane (split plane): 1529.11,20.1 20.1,20.1 20.1,1136.4 1529.11,1136.4

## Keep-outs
Keep-Out Layer:
  lines w10: -5,0 ccw(c0,0) 0,-5 ; -5,0 ccw(c0,0) 0,-5 ; -5,0 -5,1156.5 ; -5,1156.5 cw(c0,1156.5) 0,1161.5 ; -5,1156.5 cw(c0,1156.5) 0,1161.5 ; 0,-5 1549.21,-5 ; 0,1161.5 1549.21,1161.5 ; 1549.21,-5 ccw(c1549.21,0) 1554.21,0 ; 1549.21,-5 ccw(c1549.21,0) 1554.21,0 ; 1549.21,1161.5 cw(c1549.21,1156.5) 1554.21,1156.5 ; 1549.21,1161.5 cw(c1549.21,1156.5) 1554.21,1156.5 ; 1554.21,0 1554.21,1156.5
  text ".Layer_Name" at 577,-858.49 h60

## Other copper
Component Side:
  text ".Layer_Name" at 577,-858.49 h60
Solder Side:
  text ".Layer_Name" at 577,-858.49 h60

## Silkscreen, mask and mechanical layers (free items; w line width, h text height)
Top Overlay:
  lines w7: 1070,400 1100,400 ; 1165,490 1165,480 1220,425 1220,415 ; 1215,575 1215,540 1225,530
  text ".Layer_Name" at 577,-858.49 h30
Bottom Overlay:
  rectangle: 1015,25 1315,125
  text ".PRJ_Number" at 1507.02,144.99 h60
  text "-" at 1392.02,44.99 h60
  text ".PCB_Rev" at 1502.02,44.99 h60
  text ".Layer_Name" at 577,-858.49 h60
Top Paste:
  text ".Layer_Name" at 577,-858.49 h60
Bottom Paste:
  text ".Layer_Name" at 577,-858.49 h60
Top Solder:
  text ".Layer_Name" at 577,-858.49 h60
  text ".Layer_Name" at 577,-858.49 h60
Bottom Solder:
  text ".Layer_Name" at 577,-858.49 h60
Drill Guide:
  text ".Layer_Name" at 577,-858.49 h60
Mechanical 1:
  the board outline again, w10
  text ".Layer_Name" at 577,-858.49 h60
Mechanical 2:
  rectangle: 125,-400 500,-275
  rectangle: 0,-275 125,-150
  lines w7: 0,-275 1000,-275 ; 125,-400 125,-150 ; 250,-400 250,-150 ; 500,-400 500,-150 ; 750,-400 750,-150 ; 0,-400 0,-150 1000,-150 1000,-400 0,-400
  text ".Layer_Name" at 577,-858.49 h60
Mechanical 3:
  text ".Layer_Name" at 577,-858.49 h60
Mechanical 4:
  text ".Layer_Name" at 577,-858.49 h60
Mechanical 5:
  lines w10: -292,-930.17 6308,-930.17 ; -292,-726.83 6310,-726.83 ; -292,-523.5 -292,-1133.5 3713,-1133.5 6310,-1133.5 6310,-523.5 -291.5,-523.5 -291.5,-1133.5 1284,-1133.5 ; 2173,-1133.5 2173,-523.5 ; 3440,-726.83 3440,-523.5 ; 4280,-726.83 4280,-523.5 ; 4902,-1140 4902,-937.17
  text "COMPONENTS MARKED 'DNP' SHOULD NOT BE POPULATED." at 1153.5,-318.5 h60
  text "ASSEMBLY VARIANT:" at 1153,-434 h60
  text ".VariantName" at 2189,-434 h60
  text "PCB VIEWED FROM TOP SIDE" at -228.5,-655.67 h60
  text "BOARD #:" at 2248,-655.67 h60
  text ".PRJ_Number" at 2793.5,-655.67 h60
  text "REV:" at 3638,-655.67 h60
  text ".PCB_Rev" at 3929.5,-655.67 h60
  text "SVN REV:" at 4476,-655.67 h60
  text ".VersionControl_RevNumber" at 4982,-655.67 h60
  text "TID #:" at 2248,-859 h60
  text ".TID" at 2793.5,-859 h60
  text "PLOT NAME =" at -228.5,-1064.34 h60
  text ".plot_File_Name" at 577,-1064.34 h60
  text "GENERATED    :" at 2250,-1064.34 h60
  text ".Print_Date" at 3119.5,-1064.34 h60
  text ".Print_Time" at 3848.5,-1064.34 h60
  text "TEXAS INSTRUMENTS" at 5113,-1064.34 h60
Mechanical 6:
  lines w10: -292.5,-727.33 6309.5,-727.33 ; -290.5,-930.67 6309.5,-930.67 ; 1115.5,-1140.5 1115.5,-937.67 ; 1737.5,-727.33 1737.5,-524 ; 2577.5,-727.33 2577.5,-524 ; 3844.5,-1134 3844.5,-524 ; 4733.5,-1134 6309,-1134 6309,-524 -292.5,-524 -292.5,-1134 2304.5,-1134 6309.5,-1134 6309.5,-524
  text "COMPONENTS MARKED 'DNP' SHOULD NOT BE POPULATED." at 6102,-318 h60
  text ".VariantName" at 5058,-434 h60
  text "ASSEMBLY VARIANT:" at 6097,-434 h60
  text ".VersionControl_RevNumber" at 1035.5,-656.17 h60
  text "SVN REV:" at 1541.5,-656.17 h60
  text ".PCB_Rev" at 2088,-656.17 h60
  text "REV:" at 2379.5,-656.17 h60
  text ".PRJ_Number" at 3224,-656.17 h60
  text "BOARD #:" at 3769.5,-656.17 h60
  text "PCB VIEWED FROM BOTTOM SIDE" at 6246,-656.17 h60
  text ".TID" at 3224,-859.5 h60
  text "TID #:" at 3769.5,-859.5 h60
  text "TEXAS INSTRUMENTS" at 904.5,-1064.84 h60
  text ".Print_Time" at 2169,-1064.84 h60
  text ".Print_Date" at 2898,-1064.84 h60
  text "GENERATED    :" at 3767.5,-1064.84 h60
  text ".plot_File_Name" at 5440.5,-1064.84 h60
  text "PLOT NAME =" at 6246,-1064.84 h60
Mechanical 9:
  drawing of 57 lines, arcs and shapes, not listed
  text "1" at 739.84,8036.5 h70
  text "2" at 3235.5,8036.5 h70
  text "3" at 5724.84,8036.5 h70
  text "4" at 8231.51,8036.5 h70
  text "5" at 10730.5,8036.5 h70
  text "6" at 13235.5,8036.5 h70
  text "A" at -416.5,6893.5 h70
  text "A" at 14383.5,6893.5 h70
  text "B" at -416.5,4513.5 h70
  text "B" at 14383.5,4513.5 h70
  text "C" at -416.5,2138.5 h70
  text "C" at 14383.5,2138.5 h70
  text "PROJECT TITLE:" at 11343.5,277.5 h45
  text ".PRJ_Title" at 11393.5,144.17 h70
  text "DESIGNED FOR:" at 11343.5,-23.5 h45
  text ".PRJ_Customer" at 11393.5,-163.5 h70
  text "D" at -416.5,-231.5 h70
  text "D" at 14383.5,-231.5 h70
  text "FILE NAME:" at 11343.5,-323.5 h45
  text ".PCB_File_Name_No_Path" at 11393.5,-443.5 h70
  text "Texas Instruments (TI) and/or its licensors do not warrant the accuracy or completeness of this specification" at 6374,-605.34 h45
  text "ENGINEER:" at 11343.5,-613.5 h45
  text "LAYOUT BY:" at 12848.5,-613.5 h45
  text "or any information contained therein. TI and/or its licensors do not warrant that this design will meet" at 6329.01,-718 h45
  text ".PRJ_Engineer" at 11393.5,-768.49 h70
  text ".PCB_Layout" at 12899,-768.49 h70
  text "the specifications, will be suitable for your application or fit for any particular purpose, or will operate in" at 6329.01,-830.67 h45
  text ".Layer_Name" at 577,-858.49 h60
  text "ALTIUM DESIGNER VERSION:" at 12848.5,-923.5 h45
  text "an implementation. TI and/or its licensors do not warrant that the design is production worthy. You should" at 6329.01,-943.33 h45
  text "completely validate and test your design implementation to confirm the system functionality for your application." at 6374,-1056 h45
  text ".print_Scale" at 11393.5,-1056.83 h70
  text ".Application_BuildNumber" at 12899,-1056.83 h70
  text "1" at 739.84,-1263.5 h70
  text "2" at 3235.5,-1263.5 h70
  text "3" at 5724.84,-1263.5 h70
  text "4" at 8231.51,-1263.5 h70
  text "5" at 10730.5,-1263.5 h70
  text "6" at 13235.5,-1263.5 h70
Mechanical 10:
  drawing of 185 lines, arcs and shapes, not listed
  text "DESIGN INFORMATION" at 12381.02,5910 h60
  text "MIN. TRACK WIDTH:" at 11736.46,5730 h60
  text "8" at 12832.7,5730 h60
  text "MIL" at 12987.46,5730 h60
  text "MIN. CLEARANCE:" at 11736.46,5598 h60
  text "0.2" at 12772.7,5598 h60
  text "mm" at 12987.46,5598 h60
  text "MIN. VIA PAD SIZE:" at 11736.46,5466 h60
  text "24" at 12802.71,5466 h60
  text "MIL" at 12987.46,5466 h60
  text "0.05mm (2MIL)" at 12431.46,5324.29 h60
  text "MINIMUM ANNULAR RING" at 11407.23,5320 h60
  text "EXTERNAL" at 13139.46,5320 h60
  text "PER" at 11607.23,5202 h60
  text "IPC-D-275 CLASS 2 LEVEL C" at 11827.23,5202 h60
  text "MIL, HOLES" at 13315.46,5089.71 h60
  text "+/-" at 12923,5089 h60
  text "+/-" at 13777,5089 h60
  text "REGISTRATION TOLERANCES:" at 11407.23,5084 h60
  text "METAL" at 12607,5084 h60
  text "5" at 13183.2,5084 h60
  text "3" at 14016.2,5084 h60
  text "MIL" at 14132.46,5084 h60
  text "MATERIAL:" at 11332.46,4874.54 h60
  text "FR-4 High Tg" at 12318.9,4734.21 h60
  text "FR-408" at 11753.46,4725.64 h60
  text "X" at 12165.46,4725.64 h60
  text "OTHER" at 13241.46,4725.64 h60
  text "62 MIL (1.6mm) +/-10%" at 12073.56,4562.92 h60
  text "THICKNESS:" at 11407.23,4558.64 h60
  text "X" at 11945.4,4558.64 h60
  text "OTHER" at 13358.46,4558.64 h60
  text "TOLERANCE:" at 11407.23,4400.64 h60
  text "X" at 12246.53,4400.64 h60
  text "ANSI IPC-6012 TYPE 3 CLASS 2" at 12433.48,4400.64 h60
  text "OTHER +/-" at 12433.46,4244.64 h60
  text "BOW & TWIST:" at 11407.23,4087.64 h60
  text "X" at 12246.53,4087.64 h60
  text "ANSI IPC-6012 TYPE 3 CLASS 2" at 12433.48,4087.64 h60
  text "OTHER +/-" at 12433.46,3929.13 h60
  text "DRILLING:" at 11332.46,3790.64 h60
  text "REFERENCE:" at 11407.23,3673.64 h60
  text "X" at 12055.46,3673.64 h60
  text "AS SHOWN" at 12242.46,3673.64 h60
  text "X" at 12956.46,3673.64 h60
  text "NC_DRILL FILES" at 13093.46,3673.64 h60
  text "PTH MIN COPPER THICKNESS:" at 11407.23,3515.64 h60
  text "X" at 12757.46,3515.64 h60
  text "1MIL" at 12894.46,3515.64 h60
  text "OTHER" at 13391.46,3515.64 h60
  text "BOARD FINISH:" at 11332.46,3356.64 h60
  text "SILKSCREEN:" at 11487.68,3238.64 h60
  text "X" at 12436.46,3238.64 h60
  text "TOP" at 12562.46,3238.64 h60
  text "X" at 12946.46,3238.64 h60
  text "BOTTOM" at 13073.46,3238.64 h60
  text "SILKSCREEN COLOR:" at 11487.68,3071.64 h60
  text "X" at 12435.42,3071.64 h60
  text "WHITE" at 12562.46,3071.64 h60
  text "OTHER" at 13073.46,3071.64 h60
  text "SOLDER RESIST COLOR:" at 11487.68,2901.64 h60
  text "X" at 12055.42,2742.44 h60
  text "GREEN" at 12182.46,2742.44 h60
  text "BLUE" at 12773.46,2742.44 h60
  text "OTHER" at 13311.46,2742.44 h60
  text "IMMERSION GOLD (ENIG)" at 12393.46,2553.92 h60
  text "ENEPIG" at 13731,2550.64 h60
  text "SURFACE FINISH:" at 11332.46,2549.64 h60
  text "X" at 12206.51,2549.64 h60
  text "IMM. TIN/SILVER OR EQUIV" at 11662,2392.64 h60
  text "OTHER" at 13093.46,2392.64 h60
  text "ARRAY/PANEL:" at 11332.46,2213.64 h60
  text "X" at 12210,2210 h60
  text "CUT AND TRIM PER MECH LAYER 1" at 12393.46,2209.35 h60
  text "N.C. ROUTE" at 12393.46,2057.64 h60
  text "V. SCORE" at 13259.46,2057.64 h60
  text "CERTIFICATION:" at 11332.46,1920.64 h60
  text "MATERIALS AND WORKMANSHIP FOR ALL PCBS" at 12057.46,1920.64 h60
  text "TO MEET OR EXCEED THE REQUIREMENTS OF:" at 12057.46,1822.64 h60
  text "X" at 11683.96,1686.13 h60
  text "ANSI IPC-A-600F CLASS ->" at 11822.96,1686.13 h60
  text "X" at 13462.02,1686.13 h60
  text "2" at 13580.96,1686.14 h60
  text "1" at 13265.96,1684.64 h60
  text "3" at 13934.96,1684.64 h60
  text "X" at 11686.02,1526.64 h60
  text "UL 94V-0" at 11822.96,1526.64 h60
  text "X" at 12498.02,1526.64 h60
  text "RoHS" at 12634.96,1526.64 h60
  text "OTHER" at 13279.36,1526.64 h60
  text "PER ORDER" at 13676.42,1526.64 h60
  text "ADDITIONAL REQUIREMENTS:" at 11332.46,1385.64 h60
  text "MICROSECTION:" at 11407.23,1270.64 h60
  text "YES" at 12312.96,1270.64 h60
  text "REQUIRED" at 13174.46,1114.49 h60
  text "BARE BOARD ELEC. TEST:" at 11407.23,1111.64 h60
  text "NONE" at 12712.96,1111.64 h60
  text "X" at 13047.46,1111.64 h60
  text "PER ORDER" at 13766.46,1111.64 h60
  text "MANUFACTURER'S UL:" at 11407.23,954.64 h60
  text "RAIL" at 12572.96,950.35 h60
  text "METAL" at 13064.77,950.35 h60
  text "X" at 13440,950 h60
  text "SILK" at 13576.46,950.35 h60
  text ".Layer_Name" at 577,-858.49 h60
Mechanical 11:
  lines w10: -292,-930.17 6308,-930.17 ; -292,-726.83 6310,-726.83 ; -292,-523.5 -292,-1133.5 3713,-1133.5 6310,-1133.5 6310,-523.5 -291.5,-523.5 -291.5,-1133.5 1284,-1133.5 ; 2173,-1133.5 2173,-523.5 ; 3440,-726.83 3440,-523.5 ; 4280,-726.83 4280,-523.5 ; 4902,-1140 4902,-937.17
  text "ALL ARTWORK VIEWED FROM TOP SIDE" at -228.5,-655.67 h60
  text "BOARD #:" at 2248,-655.67 h60
  text ".PRJ_Number" at 2793.5,-655.67 h60
  text "REV:" at 3638,-655.67 h60
  text ".PCB_Rev" at 3929.5,-655.67 h60
  text "SVN REV:" at 4476,-655.67 h60
  text ".VersionControl_RevNumber" at 4982,-655.67 h60
  text "LAYER NAME =" at -228.5,-858.49 h60
  text "TID #:" at 2248,-859 h60
  text ".TID" at 2793.5,-859 h60
  text "PLOT NAME =" at -228.5,-1064.34 h60
  text ".plot_File_Name" at 577,-1064.34 h60
  text "GENERATED    :" at 2250,-1064.34 h60
  text ".Print_Date" at 3119.5,-1064.34 h60
  text ".Print_Time" at 3848.5,-1064.34 h60
  text "TEXAS INSTRUMENTS" at 5113,-1064.34 h60
Mechanical 12:
  drawing of 295 lines, arcs and shapes, not listed
  text "Layer" at 9655.35,7665 h60
  text "Name" at 10065.26,7665 h60
  text "Material" at 11005,7665 h60
  text "Thickness" at 11864.77,7665 h60
  text "Constant" at 12514.6,7665 h60
  text "Board Layer Stack" at 13084.46,7665 h60
  text "1" at 9655.35,7545 h60
  text "Top Overlay" at 10065.26,7545 h60
  text "2" at 9655.35,7425 h60
  text "Top Solder" at 10065.26,7425 h60
  text "Solder Resist" at 11005,7425 h60
  text "0.40mil" at 11864.77,7425 h60
  text "3.5" at 12514.6,7425 h60
  text "3" at 9655.35,7305 h60
  text "Component Side" at 10065.26,7305 h60
  text "Copper" at 11005,7305 h60
  text "1.40mil" at 11864.77,7305 h60
  text "4" at 9655.35,7185 h60
  text "Dielectric 1" at 10065.26,7185 h60
  text "FR-4" at 11005,7185 h60
  text "12.60mil" at 11864.77,7185 h60
  text "4.8" at 12514.6,7185 h60
  text "5" at 9655.35,7065 h60
  text "Ground Plane" at 10065.26,7065 h60
  text "Copper" at 11005,7065 h60
  text "1.42mil" at 11864.77,7065 h60
  text "6" at 9655.35,6945 h60
  text "Dielectric 3" at 10065.26,6945 h60
  text "5.00mil" at 11864.77,6945 h60
  text "4.2" at 12514.6,6945 h60
  text "7" at 9655.35,6825 h60
  text "Power Plane" at 10065.26,6825 h60
  text "Copper" at 11005,6825 h60
  text "1.42mil" at 11864.77,6825 h60
  text "8" at 9655.35,6705 h60
  text "Dielectric 4" at 10065.26,6705 h60
  text "10.00mil" at 11864.77,6705 h60
  text "4.2" at 12514.6,6705 h60
  text "9" at 9655.35,6585 h60
  text "Solder Side" at 10065.26,6585 h60
  text "Copper" at 11005,6585 h60
  text "1.40mil" at 11864.77,6585 h60
  text "10" at 9655.35,6465 h60
  text "Bottom Solder" at 10065.26,6465 h60
  text "Solder Resist" at 11005,6465 h60
  text "0.40mil" at 11864.77,6465 h60
  text "3.5" at 12514.6,6465 h60
  text "11" at 9655.35,6345 h60
  text "Bottom Overlay" at 10065.26,6345 h60
  text ".Layer_Name" at 577,-858.49 h60
Mechanical 13:
  text ".Layer_Name" at 577,-858.49 h60
Mechanical 14:
  text ".Layer_Name" at 577,-858.49 h60
Mechanical 15:
  text ".Layer_Name" at 577,-858.49 h60
Mechanical 16:
  text ".Layer_Name" at 577,-858.49 h60
Drill Drawing:
  circle w1: c2647.72,1006.72 r24.89
  lines w1: 2622.83,85.92 2647.72,98.36 2672.6,85.92 2660.16,110.8 2672.6,135.69 2647.72,123.25 2622.83,135.69 2635.27,110.8 2622.83,85.92 ; 2622.83,285.01 2672.6,285.01 2647.72,235.24 2622.83,285.01 ; 2622.83,384.56 2672.6,384.56 2672.6,434.33 2622.83,434.33 2622.83,384.56 ; 2622.83,558.76 2647.72,533.88 2672.6,558.76 2647.72,583.65 2622.83,558.76 ; 2622.83,683.2 2622.83,695.64 2635.27,708.08 2622.83,720.53 2622.83,732.97 2635.27,732.97 2647.72,720.53 2660.16,732.97 2672.6,732.97 2672.6,720.53 2660.16,708.08 2672.6,695.64 2672.6,683.2 2660.16,683.2 2647.72,695.64 2635.27,683.2 2622.83,683.2 ; 2622.83,844.96 2635.27,844.96 2635.27,832.52 2660.16,832.52 2660.16,844.96 2672.6,844.96 2672.6,869.85 2660.16,869.85 2660.16,882.29 2635.27,882.29 2635.27,869.85 2622.83,869.85 2622.83,844.96 ; 2622.83,1143.6 2635.27,1143.6 2647.72,1131.16 2660.16,1143.6 2672.6,1143.6 2660.16,1156.04 2672.6,1168.49 2660.16,1168.49 2647.72,1180.93 2635.27,1168.49 2622.83,1168.49 2635.27,1156.04 2622.83,1143.6
  lines w12: 2555,41.12 4673.02,41.12 ; 2555,1235.68 4673.02,1235.68 ; 2925.36,-108.2 2925.36,1385 ; 3282.36,-108.2 3282.36,1385 ; 3943.93,-108.2 3943.93,1385 ; 4228.07,-108.2 4228.07,1385 ; 2555,-108.2 4673.02,-108.2 4673.02,1385 2555,1385 2555,-108.2
  text "Symbol" at 2644.59,1280.48 h72
  text "Quantity" at 2970.16,1280.48 h72
  text "Finished Hole Size" at 3327.16,1280.48 h72
  text "Plated" at 3988.72,1280.48 h72
  text "Hole Type" at 4272.86,1280.48 h72
  text "2" at 2970.16,1131.16 h60
  text "35.04mil (0.890mm)" at 3327.16,1131.16 h60
  text "NPTH" at 3988.72,1131.16 h60
  text "Round" at 4272.86,1131.16 h60
  text "4" at 2970.16,981.84 h60
  text "7.87mil (0.200mm)" at 3327.16,981.84 h60
  text "PTH" at 3988.72,981.84 h60
  text "Round" at 4272.86,981.84 h60
  text "21" at 2970.16,832.52 h60
  text "8.00mil (0.203mm)" at 3327.16,832.52 h60
  text "PTH" at 3988.72,832.52 h60
  text "Round" at 4272.86,832.52 h60
  text "17" at 2970.16,683.2 h60
  text "10.00mil (0.254mm)" at 3327.16,683.2 h60
  text "PTH" at 3988.72,683.2 h60
  text "Round" at 4272.86,683.2 h60
  text "6" at 2970.16,533.88 h60
  text "12.00mil (0.305mm)" at 3327.16,533.88 h60
  text "PTH" at 3988.72,533.88 h60
  text "Round" at 4272.86,533.88 h60
  text "12" at 2970.16,384.56 h60
  text "30.00mil (0.762mm)" at 3327.16,384.56 h60
  text "PTH" at 3988.72,384.56 h60
  text "Round" at 4272.86,384.56 h60
  text "2" at 2970.16,235.24 h60
  text "31.50mil (0.800mm)" at 3327.16,235.24 h60
  text "PTH" at 3988.72,235.24 h60
  text "Round" at 4272.86,235.24 h60
  text "4" at 2970.16,85.92 h60
  text "66.93mil (1.700mm)" at 3327.16,85.92 h60
  text "PTH" at 3988.72,85.92 h60
  text "Round" at 4272.86,85.92 h60
  text "68 Total" at 2970.16,-63.4 h60
  text ".Layer_Name" at 577,-858.49 h60

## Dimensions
0,0 to 1549.21,0 on Mechanical 2
0,0 to 0,1156.5 on Mechanical 2
0,-400 to 1000,-400 on Mechanical 2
